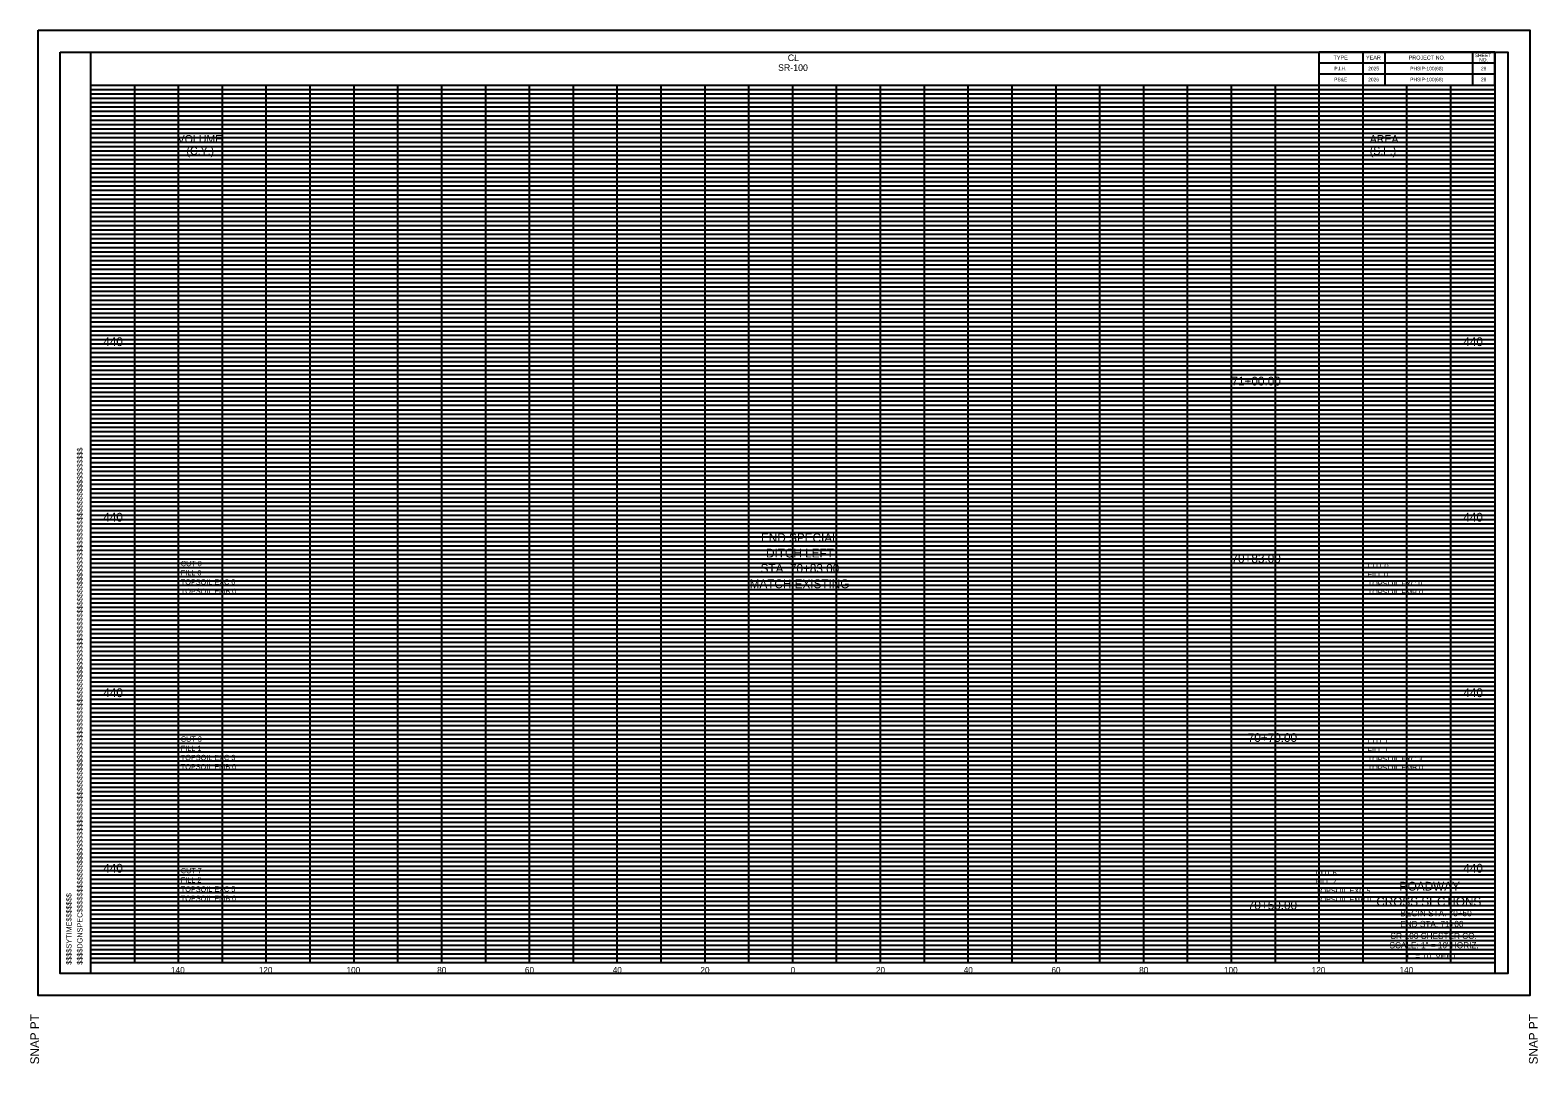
# Model space of a CAD drawing. Extents: x 37 to 1710, y 707 to 2305.
# Drawn here: x 1366.2 to 1709.8, y 1786.9 to 2022.5 of the extents above; entities that cross this region are included whole.
import ezdxf

# ---------------------------------------------------------------- set-up
doc = ezdxf.new("R2010")
doc.units = 0
for name, color, linetype in [('DESIGN - DRAINAGE - Special Ditch Width Text', 7, 'Continuous'), ('DESIGN - SHEET - Corner Text', 7, 'Continuous'), ('DESIGN - SHEET - Light Grid', 7, 'Continuous'), ('DESIGN - SHEET - Linework', 7, 'Continuous'), ('DESIGN - SHEET - Plot Shape', 7, 'Continuous'), ('DESIGN - TYPICAL - Text', 7, 'Continuous')]:
    doc.layers.add(name, color=color, linetype=linetype)

msp = doc.modelspace()

# ---------------------------------------------------------------- linework, layer by layer
at = {"layer": 'DESIGN - SHEET - Light Grid'}
for p, q in [((1380, 2009), (1700, 2009)), ((1380, 2008), (1700, 2008)), ((1380, 2007), (1700, 2007)), ((1380, 2006), (1700, 2006)), ((1380, 2005), (1700, 2005)), ((1380, 2004), (1700, 2004)), ((1380, 2003), (1700, 2003)), ((1380, 2002), (1700, 2002)), ((1380, 2001), (1700, 2001)), ((1380, 1999), (1700, 1999)), ((1380, 1998), (1700, 1998)), ((1380, 1997), (1700, 1997)), ((1380, 1996), (1700, 1996)), ((1380, 1995), (1700, 1995)), ((1380, 1994), (1700, 1994)), ((1380, 1993), (1700, 1993)), ((1380, 1992), (1700, 1992)), ((1380, 1991), (1700, 1991)), ((1380, 1989), (1700, 1989)), ((1380, 1988), (1700, 1988)), ((1380, 1987), (1700, 1987)), ((1380, 1986), (1700, 1986)), ((1380, 1985), (1700, 1985)), ((1380, 1984), (1700, 1984)), ((1380, 1983), (1700, 1983)), ((1380, 1982), (1700, 1982)), ((1380, 1981), (1700, 1981)), ((1380, 1979), (1700, 1979)), ((1380, 1978), (1700, 1978)), ((1380, 1977), (1700, 1977)), ((1380, 1976), (1700, 1976)), ((1380, 1975), (1700, 1975)), ((1380, 1974), (1700, 1974)), ((1380, 1973), (1700, 1973)), ((1380, 1972), (1700, 1972)), ((1380, 1971), (1700, 1971)), ((1380, 1969), (1700, 1969)), ((1380, 1968), (1700, 1968)), ((1380, 1967), (1700, 1967)), ((1380, 1966), (1700, 1966)), ((1380, 1965), (1700, 1965)), ((1380, 1964), (1700, 1964)), ((1380, 1963), (1700, 1963)), ((1380, 1962), (1700, 1962)), ((1380, 1961), (1700, 1961)), ((1380, 1959), (1700, 1959)), ((1380, 1958), (1700, 1958)), ((1380, 1957), (1700, 1957)), ((1380, 1956), (1700, 1956)), ((1380, 1955), (1700, 1955)), ((1380, 1954), (1700, 1954)), ((1380, 1953), (1700, 1953)), ((1380, 1952), (1700, 1952)), ((1380, 1951), (1700, 1951)), ((1380, 1949), (1700, 1949)), ((1380, 1948), (1700, 1948)), ((1380, 1947), (1700, 1947)), ((1380, 1946), (1700, 1946)), ((1380, 1945), (1700, 1945)), ((1380, 1944), (1700, 1944)), ((1380, 1943), (1700, 1943)), ((1380, 1942), (1700, 1942)), ((1380, 1941), (1700, 1941)), ((1380, 1939), (1700, 1939)), ((1380, 1938), (1700, 1938)), ((1380, 1937), (1700, 1937)), ((1380, 1936), (1700, 1936)), ((1380, 1935), (1700, 1935)), ((1380, 1934), (1700, 1934)), ((1380, 1933), (1700, 1933)), ((1380, 1932), (1700, 1932)), ((1380, 1931), (1700, 1931)), ((1380, 1929), (1700, 1929)), ((1380, 1928), (1700, 1928)), ((1380, 1927), (1700, 1927)), ((1380, 1926), (1700, 1926)), ((1380, 1925), (1700, 1925)), ((1380, 1924), (1700, 1924)), ((1380, 1923), (1700, 1923)), ((1380, 1922), (1700, 1922)), ((1380, 1921), (1700, 1921)), ((1380, 1919), (1700, 1919)), ((1380, 1918), (1700, 1918)), ((1380, 1917), (1700, 1917)), ((1380, 1916), (1700, 1916)), ((1380, 1915), (1700, 1915)), ((1380, 1914), (1700, 1914)), ((1380, 1913), (1700, 1913)), ((1380, 1912), (1700, 1912)), ((1380, 1911), (1700, 1911)), ((1380, 1909), (1700, 1909)), ((1380, 1908), (1700, 1908)), ((1380, 1907), (1700, 1907)), ((1380, 1906), (1700, 1906)), ((1380, 1905), (1700, 1905)), ((1380, 1904), (1700, 1904)), ((1380, 1903), (1700, 1903)), ((1380, 1902), (1700, 1902)), ((1380, 1901), (1700, 1901)), ((1380, 1899), (1700, 1899)), ((1380, 1898), (1700, 1898)), ((1380, 1897), (1700, 1897)), ((1380, 1896), (1700, 1896)), ((1380, 1895), (1700, 1895)), ((1380, 1894), (1700, 1894)), ((1380, 1893), (1700, 1893)), ((1380, 1892), (1700, 1892)), ((1380, 1891), (1700, 1891)), ((1380, 1889), (1700, 1889)), ((1380, 1888), (1700, 1888)), ((1380, 1887), (1700, 1887)), ((1380, 1886), (1700, 1886)), ((1380, 1885), (1700, 1885)), ((1380, 1884), (1700, 1884)), ((1380, 1883), (1700, 1883)), ((1380, 1882), (1700, 1882)), ((1380, 1881), (1700, 1881)), ((1380, 1879), (1700, 1879)), ((1380, 1878), (1700, 1878)), ((1380, 1877), (1700, 1877)), ((1380, 1876), (1700, 1876)), ((1380, 1875), (1700, 1875)), ((1380, 1874), (1700, 1874)), ((1380, 1873), (1700, 1873)), ((1380, 1872), (1700, 1872)), ((1380, 1871), (1700, 1871)), ((1380, 1869), (1700, 1869)), ((1380, 1868), (1700, 1868)), ((1380, 1867), (1700, 1867)), ((1380, 1866), (1700, 1866)), ((1380, 1865), (1700, 1865)), ((1380, 1864), (1700, 1864)), ((1380, 1863), (1700, 1863)), ((1380, 1862), (1700, 1862)), ((1380, 1861), (1700, 1861)), ((1380, 1859), (1700, 1859)), ((1380, 1858), (1700, 1858)), ((1380, 1857), (1700, 1857)), ((1380, 1856), (1700, 1856)), ((1380, 1855), (1700, 1855)), ((1380, 1854), (1700, 1854)), ((1380, 1853), (1700, 1853)), ((1380, 1852), (1700, 1852)), ((1380, 1851), (1700, 1851)), ((1380, 1849), (1700, 1849)), ((1380, 1848), (1700, 1848)), ((1380, 1847), (1700, 1847)), ((1380, 1846), (1700, 1846)), ((1380, 1845), (1700, 1845)), ((1380, 1844), (1700, 1844)), ((1380, 1843), (1700, 1843)), ((1380, 1842), (1700, 1842)), ((1380, 1841), (1700, 1841)), ((1380, 1839), (1700, 1839)), ((1380, 1838), (1700, 1838)), ((1380, 1837), (1700, 1837)), ((1380, 1836), (1700, 1836)), ((1380, 1835), (1700, 1835)), ((1380, 1834), (1700, 1834)), ((1380, 1833), (1700, 1833)), ((1380, 1832), (1700, 1832)), ((1380, 1831), (1700, 1831)), ((1380, 1829), (1700, 1829)), ((1380, 1828), (1700, 1828)), ((1380, 1827), (1700, 1827)), ((1380, 1826), (1700, 1826)), ((1380, 1825), (1700, 1825)), ((1380, 1824), (1700, 1824)), ((1380, 1823), (1700, 1823)), ((1380, 1822), (1700, 1822)), ((1380, 1821), (1700, 1821)), ((1380, 1819), (1700, 1819)), ((1380, 1818), (1700, 1818)), ((1380, 1817), (1700, 1817)), ((1380, 1816), (1700, 1816)), ((1380, 1815), (1700, 1815)), ((1380, 1814), (1700, 1814)), ((1380, 1813), (1700, 1813)), ((1380, 1812), (1700, 1812)), ((1380, 1811), (1700, 1811))]:
    msp.add_line(p, q, dxfattribs=at)
at = {"layer": 'DESIGN - SHEET - Linework'}
for p, q in [((1700, 2017.5), (1660, 2017.5)), ((1660, 2010), (1660, 2017.5)), ((1670, 2010), (1670, 2017.5)), ((1675, 2010), (1675, 2017.5)), ((1695, 2010), (1695, 2017.5)), ((1700, 2010), (1700, 2017.5)), ((1700, 2015), (1660, 2015)), ((1700, 2012.5), (1660, 2012.5)), ((1380, 2010), (1700, 2010)), ((1390, 1810), (1390, 2010)), ((1400, 1810), (1400, 2010)), ((1410, 1810), (1410, 2010)), ((1420, 1810), (1420, 2010)), ((1430, 1810), (1430, 2010)), ((1440, 1810), (1440, 2010)), ((1450, 1810), (1450, 2010)), ((1460, 1810), (1460, 2010)), ((1470, 1810), (1470, 2010)), ((1480, 1810), (1480, 2010)), ((1490, 1810), (1490, 2010)), ((1500, 1810), (1500, 2010)), ((1510, 1810), (1510, 2010)), ((1520, 1810), (1520, 2010)), ((1530, 1810), (1530, 2010)), ((1540, 1810), (1540, 2010)), ((1550, 1810), (1550, 2010)), ((1560, 1810), (1560, 2010)), ((1570, 1810), (1570, 2010)), ((1580, 1810), (1580, 2010)), ((1590, 1810), (1590, 2010)), ((1600, 1810), (1600, 2010)), ((1610, 1810), (1610, 2010)), ((1620, 1810), (1620, 2010)), ((1630, 1810), (1630, 2010)), ((1640, 1810), (1640, 2010)), ((1650, 1810), (1650, 2010)), ((1660, 1810), (1660, 2010)), ((1670, 1810), (1670, 2010)), ((1680, 1810), (1680, 2010)), ((1690, 1810), (1690, 2010)), ((1380, 2000), (1700, 2000)), ((1380, 1990), (1700, 1990)), ((1380, 1980), (1700, 1980)), ((1380, 1970), (1700, 1970)), ((1380, 1960), (1700, 1960)), ((1380, 1950), (1700, 1950)), ((1380, 1940), (1700, 1940)), ((1380, 1930), (1700, 1930)), ((1380, 1920), (1700, 1920)), ((1380, 1910), (1700, 1910)), ((1380, 1900), (1700, 1900)), ((1380, 1890), (1700, 1890)), ((1380, 1880), (1700, 1880)), ((1380, 1870), (1700, 1870)), ((1380, 1860), (1700, 1860)), ((1380, 1850), (1700, 1850)), ((1380, 1840), (1700, 1840)), ((1380, 1830), (1700, 1830)), ((1380, 1820), (1700, 1820)), ((1380, 1810), (1700, 1810))]:
    msp.add_line(p, q, dxfattribs=at)
for points in [[(1368, 2022.5), (1708, 2022.5), (1708, 1802.5), (1368, 1802.5)], [(1380, 2017.5), (1700, 2017.5), (1700, 1807.5), (1380, 1807.5)]]:
    msp.add_lwpolyline(points, close=True, dxfattribs=at)
at = {"layer": 'DESIGN - SHEET - Plot Shape'}
msp.add_lwpolyline([(1373, 2017.5), (1703, 2017.5), (1703, 1807.5), (1373, 1807.5)], close=True, dxfattribs=at)

# ---------------------------------------------------------------- texts
at = {"layer": 'DESIGN - DRAINAGE - Special Ditch Width Text'}
for s, p in [('SR-100', (1536.64, 2013.23)), ('CL', (1538.85, 2015.46))]:
    msp.add_text(s, height=1.5, rotation=359.6675, dxfattribs=at).set_placement(p)
at = {"layer": 'DESIGN - SHEET - Corner Text'}
for s, height, p in [('P.I.H.', 0.8, (1663.45, 2013.35)), ('2025', 0.8, (1671.16, 2013.35)), ('PHSIP-100(68)', 0.8, (1680.75, 2013.35)), ('28', 0.8, (1696.86, 2013.35)), ('PS&E', 0.8, (1663.42, 2010.85)), ('2026', 0.8, (1671.16, 2010.85)), ('PHSIP-100(68)', 0.8, (1680.75, 2010.85)), ('28', 0.8, (1696.86, 2010.85)), ('ROADWAY ', 2, (1678.23, 1826.4)), ('CROSS SECTIONS', 2, (1673.01, 1822.9)), ('BEGIN STA. 70+50', 1.4, (1678.47, 1820.55)), ('END STA. 71+00', 1.4, (1678.47, 1818.1)), ('SCALE: 1" = 10\' HORIZ.', 1.4, (1676.02, 1813.26)), ('SR-100 CHESTER CO.', 1.4, (1676.25, 1815.37)), ('       1" = 10\' VERT.   ', 1.4, (1676.02, 1810.81))]:
    msp.add_text(s, height=height, dxfattribs=at).set_placement(p)
for s, height, p in [('$$$$DGNSPEC$$$$$$$$$$$$$$$$$$$$$$$$$$$$$$$$$$$$$$$$$$$$$$$$$$$$$$$$$$$$$$$$$$$$$$$$$$$$$$$$$$$$$$$$$$$$$$$$$$$$$$$$$$$$$$$$$$$', 1.2, (1378.1, 1809.5)), ('$$$$SYTIME$$$$$$$', 1.2, (1375.6, 1809.5)), ('SNAP PT  ', 2, (1368.2, 1786.8)), ('SNAP PT  ', 2, (1709.8, 1786.8))]:
    msp.add_text(s, height=height, rotation=90, dxfattribs=at).set_placement(p)
at = {"layer": 'DESIGN - SHEET - Light Grid'}
for s, height, p in [('TYPE', 0.9, (1663.26, 2015.8)), ('YEAR', 0.9, (1670.66, 2015.8)), ('PROJECT NO.', 0.9, (1680.38, 2015.8)), ('SHEET', 0.8, (1695.47, 2016.35)), ('NO.', 0.8, (1696.47, 2015.35))]:
    msp.add_text(s, height=height, dxfattribs=at).set_placement(p)
at = {"layer": 'DESIGN - TYPICAL - Text'}
for s, height, p in [('VOLUME', 1.8, (1399.79, 1996.79)), ('AREA ', 1.8, (1671.52, 1996.79)), ('   (C.Y.)', 1.8, (1399.79, 1994.09)), ('(S.F.)', 1.8, (1671.52, 1994.09)), ('440', 2, (1382.84, 1950.5)), ('440', 2, (1692.84, 1950.5)), ('71+00.00', 2, (1640, 1941.52)), ('440', 2, (1382.84, 1910.5)), ('440', 2, (1692.84, 1910.5)), ('END SPECIAL ', 2, (1532.76, 1905.82)), ('DITCH LEFT', 2, (1533.91, 1902.32)), ('CUT 0', 1.2, (1400.51, 1900.34)), ('STA. 70+83.00', 2, (1532.67, 1898.82)), ('70+83.00', 2, (1640, 1901.1)), ('CUT 0', 1.2, (1671, 1899.84)), ('TOPSOIL EXC 0', 1.2, (1400.51, 1896.14)), ('FILL 0', 1.2, (1400.51, 1898.24)), ('MATCH EXISTING', 2, (1530.17, 1895.32)), ('FILL 0', 1.2, (1671, 1897.84)), ('TOPSOIL EMB 0', 1.2, (1400.51, 1894.04)), ('TOPSOIL EXC 0', 1.2, (1671.06, 1895.77)), ('TOPSOIL EMB 0', 1.2, (1671.06, 1893.78)), ('440', 2, (1382.84, 1870.5)), ('440', 2, (1692.84, 1870.5)), ('CUT 3', 1.2, (1400.51, 1860.34)), ('FILL 1', 1.2, (1400.51, 1858.24)), ('     70+70.00     ', 2, (1640, 1860.28)), ('CUT 1', 1.2, (1671, 1859.84)), ('TOPSOIL EXC 3', 1.2, (1400.51, 1856.14)), ('TOPSOIL EXC 3', 1.2, (1671.06, 1855.77)), ('FILL 1', 1.2, (1671, 1857.84)), ('TOPSOIL EMB 0', 1.2, (1400.51, 1854.04)), ('TOPSOIL EMB 0', 1.2, (1671.06, 1853.78)), ('440', 2, (1382.84, 1830.5)), ('440', 2, (1692.84, 1830.5)), ('CUT 7', 1.2, (1400.51, 1830.34)), ('FILL 2', 1.2, (1400.51, 1828.24)), ('CUT 6', 1.2, (1659.19, 1829.84)), ('FILL 2', 1.2, (1659.19, 1827.84)), ('TOPSOIL EXC 5', 1.2, (1400.51, 1826.14)), ('TOPSOIL EMB 0', 1.2, (1400.51, 1824.04)), ('TOPSOIL EXC 5', 1.2, (1659.25, 1825.77)), ('TOPSOIL EMB 0', 1.2, (1659.25, 1823.78)), ('     70+50.00     ', 2, (1640, 1822.09)), ('     140     ', 1.4, (1395.68, 1807.6)), ('     120     ', 1.4, (1415.68, 1807.6)), ('     100     ', 1.4, (1435.68, 1807.6)), ('     80     ', 1.4, (1456.35, 1807.6)), ('     60     ', 1.4, (1476.35, 1807.6)), ('     40     ', 1.4, (1496.35, 1807.6)), ('     20     ', 1.4, (1516.35, 1807.6)), ('     0     ', 1.4, (1536.9, 1807.6)), ('     0     ', 1.4, (1536.9, 1807.6)), ('     20     ', 1.4, (1556.35, 1807.6)), ('     40     ', 1.4, (1576.35, 1807.6)), ('     60     ', 1.4, (1596.35, 1807.6)), ('     80     ', 1.4, (1616.35, 1807.6)), ('     100     ', 1.4, (1635.68, 1807.6)), ('     120     ', 1.4, (1655.68, 1807.6)), ('     140     ', 1.4, (1675.68, 1807.6))]:
    msp.add_text(s, height=height, dxfattribs=at).set_placement(p)

doc.saveas('drawing.dxf')
